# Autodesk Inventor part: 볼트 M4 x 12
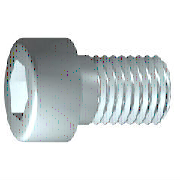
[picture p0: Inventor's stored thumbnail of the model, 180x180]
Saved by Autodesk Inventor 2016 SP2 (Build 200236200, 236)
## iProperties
IsCustomPart: 0
Created: 2012-02
Part Number: 볼트 M4 x 12
Material: 강철, 연강
Description: 6각 소켓 머리 캡 나사
Document SubType Name: Modeling
Standard: ISO 4762
Designer: mduedu
Standard Revision: Fourth edition 2004-03-01
Standards Organization: ISO
Language: ko-KR
Size Designation: M4 x 12
Categories: <MemberInstance><Categories><Category DisplayName="조임쇠" InternalName="e4da775c-781d-43d5-af7c-5136215cf5a6" Mnemonic="FSTN"><Category DisplayName="볼트" InternalN
Density: 7.75 g/cm^3
Appearance: 강철
Author: mduedu
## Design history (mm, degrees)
sketch "스케치1"
  geometry: L1 (-1, 0)-(12, 0); L2 (12, 0)-(12, 2); L3 (12, 2)-(1.75, 2); L4 (1.75, 2)-(1.32, 2); L5 (1.32, 2)-(0, 2); L6 (0, 2)-(0, 3.5); L7 (0, 3.5)-(-4, 3.5); L8 (-4, 3.5)-(-4, 1.732); L9 (-4, 1.732)-(-2, 1.732); L10 (-2, 1.732)-(-1, 0); L11 (-7.2, 0)-(15.2, 0) reference; L12 (0, -0.7)-(0, 4.2) reference; L13 (1.75, 2)-(0, 2)
  constraints: 22 end point, 6 parallel, 2 collinear, 2 perpendicular, 1 horizontal, 1 point on line
  dimensions: "d1" = 10.25 distance from line of L3.end L2 (= GEL); "d2" = 0.42952 distance of L4.end L3.end (computed from GAL); "d3" = 4 distance between parallel lines of L8 L6 (= KOH); "d4" = 2 distance of L8.end L9.end (= INTI); "d5" = 60 deg angle of L10 L1; "d6" = 4 diameter of L3 L1 (= GD); "d7" = 4 diameter of L5 L1 (= BDM); "d8" = 3.4641 diameter of L9 L1 (= 1.1547 x SW); "d9" = 7 diameter of L7 L1 (= KOD); "d26" = 12 distance between parallel lines of L12 L2 (= NLG)
revolve "본체" sketch "스케치1" stored, may be unused: angle "d10" = 90 deg
sketch "스케치2"
  geometry: L1 (0, -4.9)-(0, 4.9) reference; L2 (-4.9, 0)-(4.9, 0) reference; L3 (1.732, 0)-(0.866, -1.5); L4 (0.866, -1.5)-(-0.866, -1.5); L5 (-0.866, -1.5)-(-1.732, 0); L6 (-1.732, 0)-(-0.866, 1.5); L7 (-0.866, 1.5)-(0.866, 1.5); L8 (0.866, 1.5)-(1.732, 0); 2 further points
  constraints: 12 end point, 1 coincident, 1 horizontal alignment, 1 point on line, 12 other
extrude "슬롯" join sketch "스케치2" stored distance "d11" = 10; taper "d12" = 0 deg
workplane "Work Plane1"
fillet "Fillet2" dims "d30" = 0.1 (= R)
body "Solid1"
fillet "모깎기1" dims "d17" = 0.4 (= RR)
feature "스레드" dims "d13" = 10.25 (= GEL), "d14" = 0
chamfer "모따기1" distance "d15" = 0.42941 (= -0.5 x SPD + 0.5 x GD); stored, may be unused: second distance "d16" = 0.42941 (= GUL), angle "d27" = 45 deg
other parameters: "GD" = 4 [user parameter; used in 2 equation terms], "NLG" = 12 [user parameter; used in 1 equation term], "GEL" = 10.25 [user parameter; used in 2 equation terms], "KOD" = 7 [user parameter; used in 1 equation term], "KOH" = 4 [user parameter; used in 1 equation term], "INTI" = 2 [user parameter; used in 1 equation term], "GAL" = 0.42941 (= 0.61345 x PTC) [user parameter; used in 1 equation term], "GUL" = 0.42941 (= 0.61345 x PTC) [user parameter; used in 1 equation term], "BDM" = 4 (= NND) [user parameter; used in 1 equation term], "SW" = 3 [user parameter; used in 2 equation terms], "RR" = 0.4 [user parameter; used in 1 equation term], "SPD" = 3.14117 (= NND - 1.2269 x PTC) [user parameter; used in 1 equation term], "d19" = 0, "d28" = 0, "d29" = 0, "R" = 0.1 [user parameter; used in 1 equation term], "TOA" = 30 deg [user parameter], "GD1" = 3.14117 (= THREADDIA - 1.2269 x PTC) [user parameter], "THREADDIA" = 4 [user parameter; used in 1 equation term], "FAWI" = 45 deg [user parameter], "TPU" = 14.28571 (computed from PTC) [user parameter], "PTC" = 0.7 [user parameter; used in 5 equation terms], "NND" = 4 [user parameter; used in 2 equation terms], "E0" = 3.465 (= 1.155 x SW) [user parameter]
